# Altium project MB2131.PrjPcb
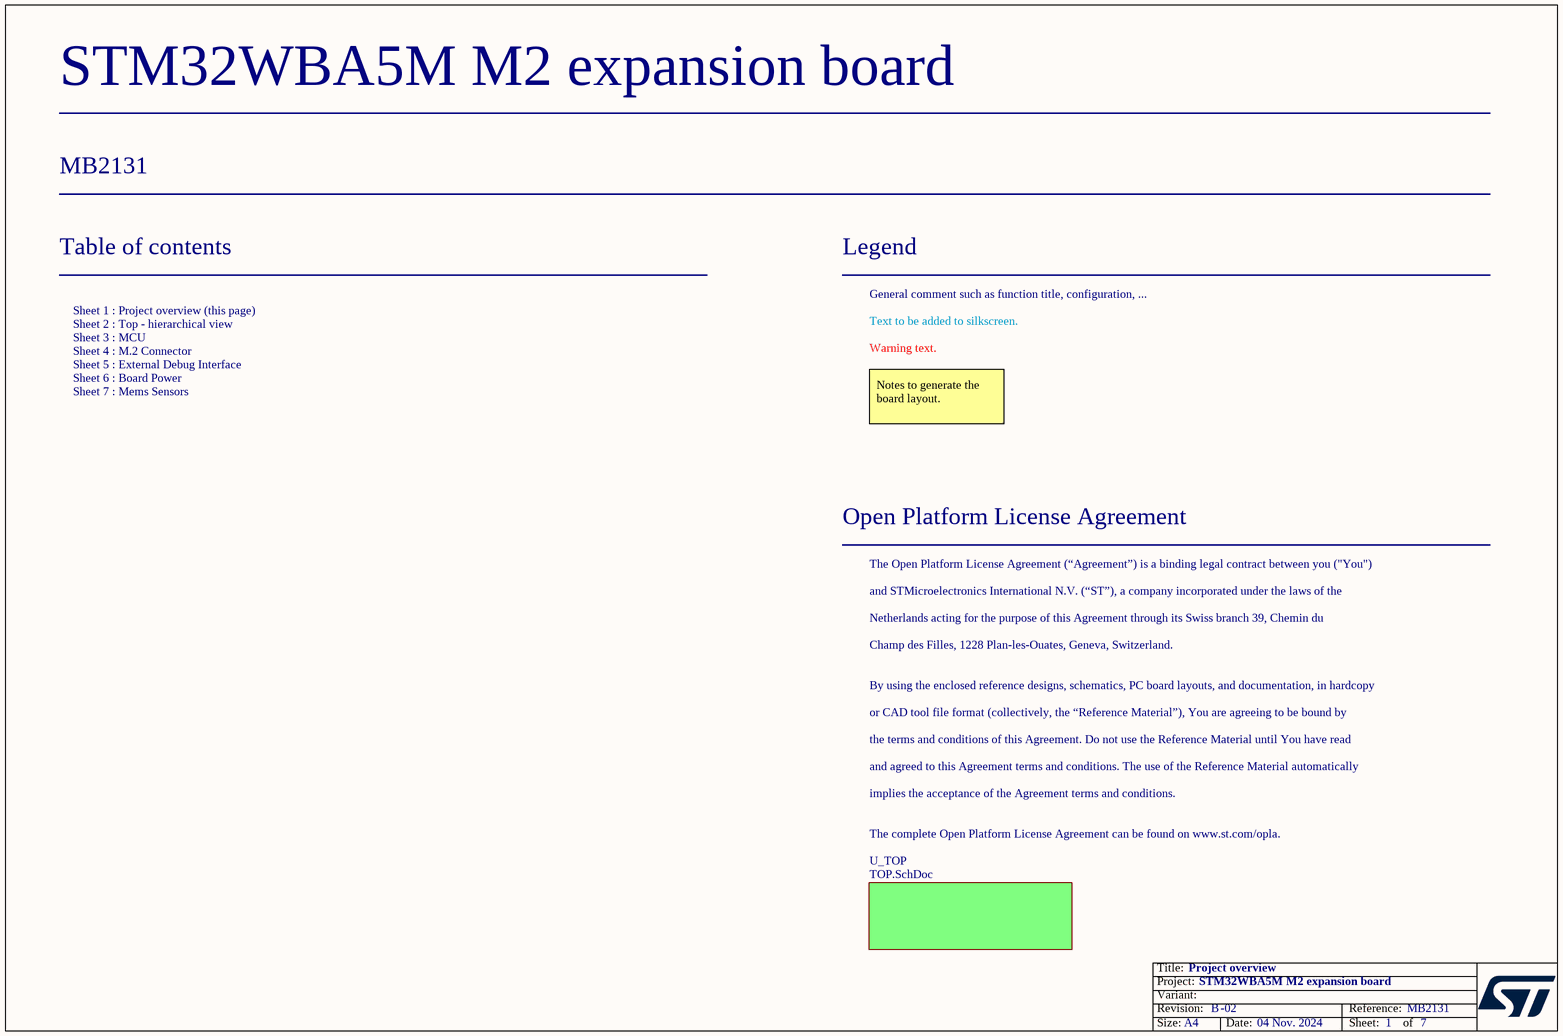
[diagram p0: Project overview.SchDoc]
Board_Assembly_Revision: 02; Board_Document_Date: 04 Nov. 2024; Board_Name: STM32WBA5M M2 expansion board; Board_PCB_Revision: B; Board_Reference: MB2131
7 sheets, 81 parts. Net scope: flat (ports and power ports of the same name join across sheets).
Board file: MB2131.PcbDoc
Sheets:
  Project overview.SchDoc
    U_TOP = Top.SchDoc
      U_MCU = MCU.SchDoc
      U_Board_Power = Board_Power.SchDoc
      U_External_Debug_Interface = External_Debug_Interface.SchDoc
      U_Mems = Mems.SchDoc
      U_M2 = M2.SchDoc

## Sheet Project overview.SchDoc: Project overview
size A4; Date: Not used; ApprovedBy: Not used; CheckedBy: Not used; Author: Not used; CompanyName: STMicroelectronics; DrawnBy: Not used; Engineer: Not used; Organization: Not used; Address1: Not used; Address2: Not used; Address3: Not used; Address4: Not used; DocumentNumber: 1; Revision: Not used; SheetNumber: 1; SheetTotal: 7

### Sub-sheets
U_TOP = TOP.SchDoc: no entries

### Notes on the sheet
- Table of contents
- Legend
- General comment such as function title, configuration, ...
- Text to be added to silkscreen.
- Warning text.
- Notes to generate the board layout.
- Open Platform License Agreement
- The Open Platform License Agreement (“Agreement”) is a binding legal contract between you ("You")
- and STMicroelectronics International N.V. (“ST”), a company incorporated under the laws of the
- Netherlands acting for the purpose of this Agreement through its Swiss branch 39, Chemin du
- Champ des Filles, 1228 Plan-les-Ouates, Geneva, Switzerland.
- Sheet 1 : Project overview (this page)
  Sheet 2 : Top - hierarchical view
  Sheet 3 : MCU
  Sheet 4 : M.2 Connector
  Sheet 5 : External Debug Interface
  Sheet 6 : Board Power
  Sheet 7 : Mems Sensors
- By using the enclosed reference designs, schematics, PC board layouts, and documentation, in hardcopy
- or CAD tool file format (collectively, the “Reference Material”), You are agreeing to be bound by
- the terms and conditions of this Agreement. Do not use the Reference Material until You have read
- and agreed to this Agreement terms and conditions. The use of the Reference Material automatically
- implies the acceptance of the Agreement terms and conditions.
- The complete Open Platform License Agreement can be found on www.st.com/opla.

## Sheet Top.SchDoc: Top - hierarchical view
size A4; Date: Not used; ApprovedBy: Not used; CheckedBy: Not used; Author: Not used; CompanyName: STMicroelectronics; DrawnBy: Not used; Engineer: Not used; Organization: Not used; Address1: Not used; Address2: Not used; Address3: Not used; Address4: Not used; DocumentNumber: Not used; Revision: Not used; SheetNumber: 2; SheetTotal: 7
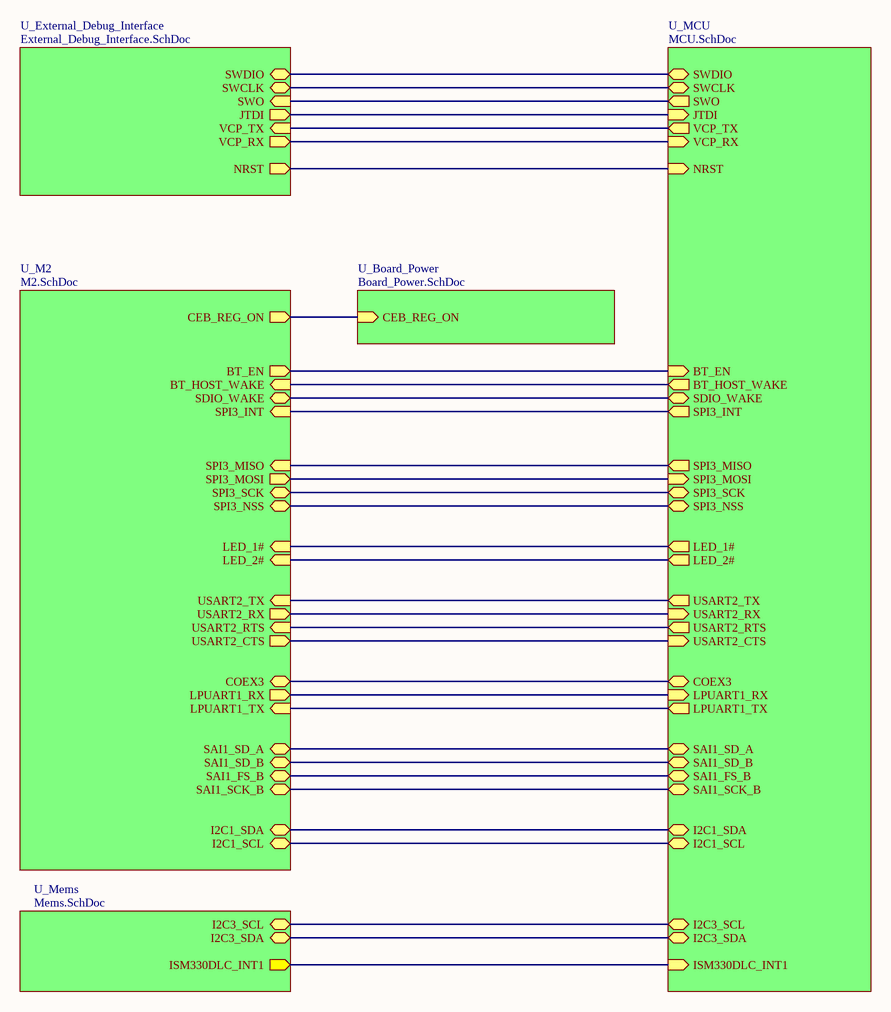
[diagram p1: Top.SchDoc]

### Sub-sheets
U_Board_Power = Board_Power.SchDoc: CEB_REG_ON (in)
U_External_Debug_Interface = External_Debug_Interface.SchDoc: SWDIO (bidir), SWCLK (bidir), SWO (in), JTDI (out), VCP_TX (in), NRST (out), VCP_RX (out)
U_M2 = M2.SchDoc: SPI3_SCK (bidir), SPI3_MISO (in), SPI3_NSS (bidir), SPI3_MOSI (out), BT_HOST_WAKE (in), SPI3_INT (in), SAI1_SD_B (bidir), SAI1_SD_A (bidir), SAI1_FS_B (bidir), SAI1_SCK_B (bidir), LED_2# (in), LED_1# (in), COEX3 (bidir), LPUART1_RX (out), LPUART1_TX (in), SDIO_WAKE (bidir), CEB_REG_ON (out), BT_EN (out), USART2_RX (out), USART2_RTS (in), USART2_CTS (out), USART2_TX (in), I2C1_SDA (bidir), I2C1_SCL (bidir)
U_MCU = MCU.SchDoc: ISM330DLC_INT1 (in), I2C3_SCL (bidir), I2C3_SDA (bidir), SWCLK (bidir), SWDIO (bidir), VCP_TX (out), VCP_RX (in), SPI3_SCK (bidir), SPI3_MISO (out), SPI3_NSS (bidir), SPI3_MOSI (in), SWO (out), JTDI (in), SPI3_INT (out), BT_HOST_WAKE (out), SAI1_SD_B (bidir), SAI1_SD_A (bidir), SAI1_FS_B (bidir), SAI1_SCK_B (bidir), LED_1# (out), LED_2# (out), COEX3 (bidir), LPUART1_RX (in), LPUART1_TX (out), SDIO_WAKE (bidir), NRST (in), BT_EN (in), USART2_RX (in), USART2_RTS (out), USART2_CTS (in), USART2_TX (out), I2C1_SCL (bidir), I2C1_SDA (bidir)
U_Mems = Mems.SchDoc: ISM330DLC_INT1 (out), I2C3_SCL (bidir), I2C3_SDA (bidir)

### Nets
(unnamed): sheet U_MCU/ISM330DLC_INT1, sheet U_Mems/ISM330DLC_INT1
(unnamed): sheet U_MCU/I2C3_SCL, sheet U_Mems/I2C3_SCL  [a separate net that carries the same name]
(unnamed): sheet U_MCU/I2C3_SDA, sheet U_Mems/I2C3_SDA  [a separate net that carries the same name]
(unnamed): sheet U_MCU/SWCLK, sheet U_External_Debug_Interface/SWCLK  [a separate net that carries the same name]
(unnamed): sheet U_MCU/SWDIO, sheet U_External_Debug_Interface/SWDIO  [a separate net that carries the same name]
(unnamed): sheet U_MCU/VCP_TX, sheet U_External_Debug_Interface/VCP_TX  [a separate net that carries the same name]
(unnamed): sheet U_MCU/VCP_RX, sheet U_External_Debug_Interface/VCP_RX  [a separate net that carries the same name]
(unnamed): sheet U_MCU/SPI3_SCK, sheet U_M2/SPI3_SCK  [a separate net that carries the same name]
(unnamed): sheet U_MCU/SPI3_MISO, sheet U_M2/SPI3_MISO  [a separate net that carries the same name]
(unnamed): sheet U_MCU/SPI3_NSS, sheet U_M2/SPI3_NSS  [a separate net that carries the same name]
(unnamed): sheet U_MCU/SPI3_MOSI, sheet U_M2/SPI3_MOSI  [a separate net that carries the same name]
(unnamed): sheet U_MCU/SWO, sheet U_External_Debug_Interface/SWO  [a separate net that carries the same name]
(unnamed): sheet U_MCU/JTDI, sheet U_External_Debug_Interface/JTDI  [a separate net that carries the same name]
(unnamed): sheet U_MCU/SPI3_INT, sheet U_M2/SPI3_INT  [a separate net that carries the same name]
(unnamed): sheet U_MCU/BT_HOST_WAKE, sheet U_M2/BT_HOST_WAKE  [a separate net that carries the same name]
(unnamed): sheet U_MCU/SAI1_SD_B, sheet U_M2/SAI1_SD_B  [a separate net that carries the same name]
(unnamed): sheet U_MCU/SAI1_SD_A, sheet U_M2/SAI1_SD_A  [a separate net that carries the same name]
(unnamed): sheet U_MCU/SAI1_FS_B, sheet U_M2/SAI1_FS_B  [a separate net that carries the same name]
(unnamed): sheet U_MCU/SAI1_SCK_B, sheet U_M2/SAI1_SCK_B  [a separate net that carries the same name]
(unnamed): sheet U_MCU/LED_1#, sheet U_M2/LED_1#  [a separate net that carries the same name]
(unnamed): sheet U_MCU/LED_2#, sheet U_M2/LED_2#  [a separate net that carries the same name]
(unnamed): sheet U_MCU/COEX3, sheet U_M2/COEX3  [a separate net that carries the same name]
(unnamed): sheet U_MCU/LPUART1_RX, sheet U_M2/LPUART1_RX  [a separate net that carries the same name]
(unnamed): sheet U_MCU/LPUART1_TX, sheet U_M2/LPUART1_TX  [a separate net that carries the same name]
(unnamed): sheet U_MCU/SDIO_WAKE, sheet U_M2/SDIO_WAKE  [a separate net that carries the same name]
(unnamed): sheet U_MCU/NRST, sheet U_External_Debug_Interface/NRST  [a separate net that carries the same name]
(unnamed): sheet U_MCU/BT_EN, sheet U_M2/BT_EN  [a separate net that carries the same name]
(unnamed): sheet U_MCU/USART2_RX, sheet U_M2/USART2_RX  [a separate net that carries the same name]
(unnamed): sheet U_MCU/USART2_RTS, sheet U_M2/USART2_RTS  [a separate net that carries the same name]
(unnamed): sheet U_MCU/USART2_CTS, sheet U_M2/USART2_CTS  [a separate net that carries the same name]
(unnamed): sheet U_MCU/USART2_TX, sheet U_M2/USART2_TX  [a separate net that carries the same name]
(unnamed): sheet U_MCU/I2C1_SCL, sheet U_M2/I2C1_SCL  [a separate net that carries the same name]
(unnamed): sheet U_MCU/I2C1_SDA, sheet U_M2/I2C1_SDA  [a separate net that carries the same name]
(unnamed): sheet U_Board_Power/CEB_REG_ON, sheet U_M2/CEB_REG_ON  [a separate net that carries the same name]

## Sheet MCU.SchDoc: MCU
size A4; Date: Not used; ApprovedBy: Not used; CheckedBy: Not used; Author: Not used; CompanyName: STMicroelectronics; DrawnBy: Not used; Engineer: Not used; Organization: Not used; Address1: Not used; Address2: Not used; Address3: Not used; Address4: Not used; DocumentNumber: Not used; Revision: Not used; SheetNumber: 3; SheetTotal: 7
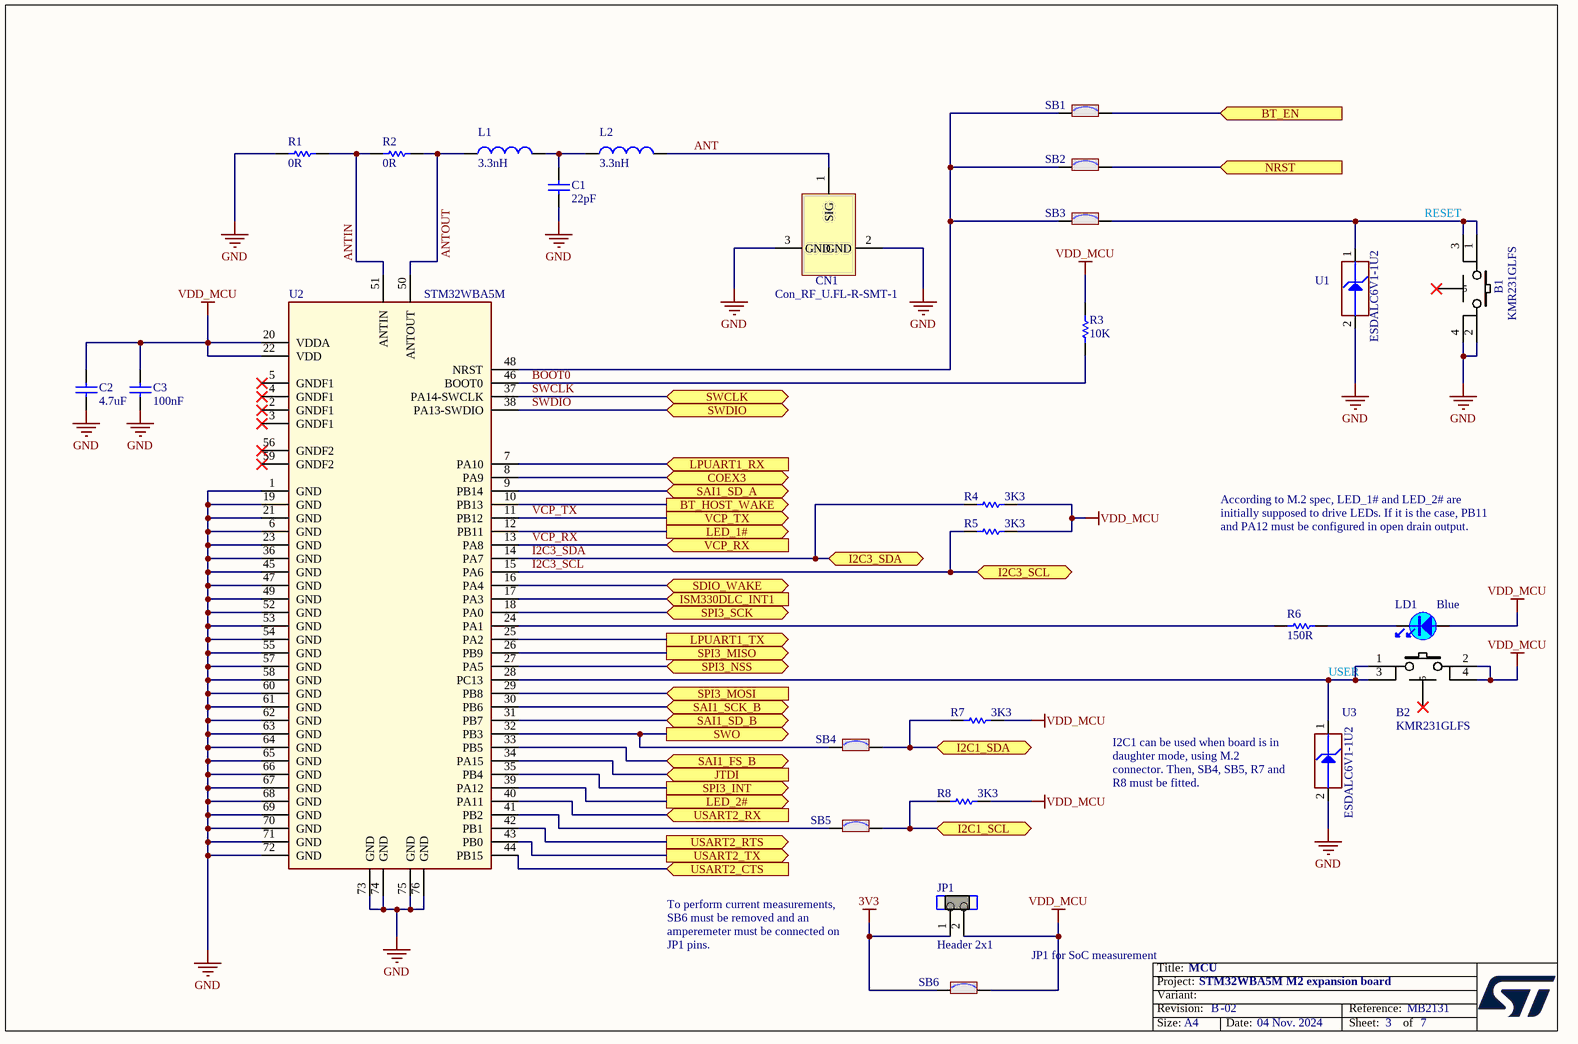
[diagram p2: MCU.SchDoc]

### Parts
B1  value KMR231GLFS  [SWI_C&K_Y78B23110FP__ITT_KMR231GLFS]  (hidden comment: SW-PUSH-CMS_KMR2_BLACK)
B2  value KMR231GLFS  [SWI_C&K_Y78B23110FP__ITT_KMR231GLFS]  (hidden comment: SW-PUSH-CMS_KMR2_BLACK)
C1  value 22pF  [C0402]  (hidden comment: Capacitor)
C2  value 4.7uF  [C0603]  (hidden comment: Capacitor)
C3  value 100nF  [C0402]  (hidden comment: Capacitor)
CN1  value Con_RF_U.FL-R-SMT-1  [CON_HRS_U.FL-R-SMT-1]  (hidden comment: U.FL-R-SMT-1)
JP1  value Header 2x1  [CON_WP_707-2-02-2-20-00]  (hidden comment: Jumper_Header1.27 2x1 Fitted)
L1  value 3.3nH  [C0402]  (hidden comment: Inductor)
L2  value 3.3nH  [C0402]  (hidden comment: Inductor)
LD1  value Blue  [LED_0603_OSRAM_LB-Q39G-L2OO-35-1_BLUE_1A2K_H0P4]  (hidden comment: LED_blue)
R1  value 0R  [R0402]  (hidden comment: Resistor)
R2  value 0R  [R0402]  (hidden comment: Resistor)
R3  value 10K  [R0402]  (hidden comment: Resistor)
R4  value 3K3  [R0402]  (hidden comment: Resistor)
R5  value 3K3  [R0402]  (hidden comment: Resistor)
R6  value 150R  [R0402]  (hidden comment: Resistor)
R7  value 3K3  [R0402]  (hidden comment: Resistor)
R8  value 3K3  [R0402]  (hidden comment: Resistor)
SB1  SB_ON  [SOLDER-BRIDGE_R0402-0R]  (value not drawn)
SB2  SB_ON  [SOLDER-BRIDGE_R0402-0R]  (value not drawn)
SB3  SB_ON  [SOLDER-BRIDGE_R0402-0R]  (value not drawn)
SB4  SB_ON  [SOLDER-BRIDGE_R0402-0R]  (value not drawn)
SB5  SB_ON  [SOLDER-BRIDGE_R0402-0R]  (value not drawn)
SB6  SB_ON  [SOLDER-BRIDGE_R0402-0R]  (value not drawn)
U1  value ESDALC6V1-1U2  [ESD_ST0201]  (hidden comment: ESD-TRANSIL)
U2  STM32WBA5M  [MOD_STM_76P_8X12P5_H1P37]
U3  value ESDALC6V1-1U2  [ESD_ST0201]  (hidden comment: ESD-TRANSIL)

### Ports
BT_EN (in), BT_HOST_WAKE (out), COEX3 (bidir), I2C1_SCL (bidir), I2C1_SDA (bidir), I2C3_SCL (bidir), I2C3_SDA (bidir), ISM330DLC_INT1 (in), JTDI (in), LED_1# (out), LED_2# (out), LPUART1_RX (in), LPUART1_TX (out), NRST (in), SAI1_FS_B (bidir), SAI1_SCK_B (bidir), SAI1_SD_A (bidir), SAI1_SD_B (bidir), SDIO_WAKE (bidir), SPI3_INT (out), SPI3_MISO (out), SPI3_MOSI (in), SPI3_NSS (bidir), SPI3_SCK (bidir), SWCLK (bidir), SWDIO (bidir), SWO (out), USART2_CTS (in), USART2_RTS (out), USART2_RX (in), USART2_TX (out), VCP_RX (in), VCP_TX (out)

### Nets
3V3: JP1.1 SB6.1
GND: B1.2 B1.4 C1.1 C2.1 C3.1 CN1.2(GND) CN1.3(GND) R1.1 U1.2(GND) U2.1(GND) U2.6(GND) U2.19(GND) U2.21(GND) U2.23(GND) U2.36(GND) U2.45(GND) U2.47(GND) U2.49(GND) U2.52(GND) U2.53(GND) U2.54(GND) U2.55(GND) U2.57(GND) U2.58(GND) U2.60(GND) U2.61(GND) U2.62(GND) U2.63(GND) U2.64(GND) U2.65(GND) U2.66(GND) U2.67(GND) U2.68(GND) U2.69(GND) U2.70(GND) U2.71(GND) U2.72(GND) U2.73(GND) U2.74(GND) U2.75(GND) U2.76(GND) U3.2(GND)
VDD_MCU: B2.2 B2.4 C2.2 C3.2 JP1.2 LD1.1 R3.2 R4.1 R5.1 R7.1 R8.1 SB6.2 U2.20(VDDA) U2.22(VDD)
ANT: CN1.1(SIG) L2.2
ANTIN: R1.2 R2.1 U2.51(ANTIN)
ANTOUT: L1.1 R2.2 U2.50(ANTOUT)
BOOT0: R3.1 U2.46(BOOT0)
I2C3_SCL: R5.2 U2.15(PA6) ; port I2C3_SCL
I2C3_SDA: R4.2 U2.14(PA7) ; port I2C3_SDA
JTDI: U2.34(PA15) ; port JTDI
NRST: SB2.2 ; port NRST
SPI3_MISO: U2.26(PB9) ; port SPI3_MISO
SPI3_MOSI: U2.29(PB8) ; port SPI3_MOSI
SPI3_NSS: U2.27(PA5) ; port SPI3_NSS
SPI3_SCK: U2.18(PA0) ; port SPI3_SCK
SWCLK: U2.37(PA14-SWCLK) ; port SWCLK
SWDIO: U2.38(PA13-SWDIO) ; port SWDIO
SWO: SB4.1 U2.32(PB3) ; port SWO
VCP_RX: U2.13(PA8) ; port VCP_RX
VCP_TX: U2.11(PB12) ; port VCP_TX
NetB1_1: B1.1 B1.3 SB3.2 U1.1(IO1)
NetB2_1: B2.1 B2.3 U2.28(PC13) U3.1(IO1)
NetC1_2: C1.2 L1.2 L2.1
NetCN2_6: U2.12(PB11) ; port LED_1#
NetCN2_8: U2.30(PB6) ; port SAI1_SCK_B
NetCN2_10: U2.33(PB5) ; port SAI1_FS_B
NetCN2_12: U2.31(PB7) ; port SAI1_SD_B
NetCN2_14: U2.9(PB14) ; port SAI1_SD_A
NetCN2_16: U2.39(PA12) ; port LED_2#
NetCN2_20: U2.10(PB13) ; port BT_HOST_WAKE
NetCN2_22: U2.43(PB0) ; port USART2_TX
NetCN2_32: U2.40(PA11) ; port USART2_RX
NetCN2_34: U2.42(PB1) ; port USART2_RTS
NetCN2_36: U2.44(PB15) ; port USART2_CTS
NetCN2_54: SB1.2 ; port BT_EN
NetCN2_58: R7.2 SB4.2 ; port I2C1_SDA
NetCN2_60: R8.2 SB5.2 ; port I2C1_SCL
NetCN2_62: U2.35(PB4) ; port SPI3_INT
NetLD1_2: LD1.2 R6.2
NetR6_1: R6.1 U2.24(PA1)
NetSB1_1: SB1.1 SB2.1 SB3.1 U2.48(NRST)
NetSB5_1: SB5.1 U2.41(PB2)
NetSB11_2: U2.16(PA4) ; port SDIO_WAKE
NetSB12_1: U2.8(PA9) ; port COEX3
NetSB13_1: U2.25(PA2) ; port LPUART1_TX
NetSB14_1: U2.7(PA10) ; port LPUART1_RX
NetU2_17: U2.17(PA3) ; port ISM330DLC_INT1

Not connected (* = marked no-connect by the designer): B1 5*; B2 5*; U2 2(GNDF1)* 3(GNDF1)* 4(GNDF1)* 5(GNDF1)* 56(GNDF2)* 59(GNDF2)*

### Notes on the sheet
- (near B1) RESET
- According to M.2 spec, LED_1# and LED_2# are initially supposed to drive LEDs. If it is the case, PB11 and PA12 must be configured in open drain output.
- USER
- (near U3) I2C1 can be used when board is in  daughter mode, using M.2 connector. Then, SB4, SB5, R7 and R8 must be fitted.
- To perform current measurements, SB6 must be removed and an amperemeter must be connected on JP1 pins.
- JP1 for SoC measurement

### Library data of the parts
B1 B2 = MCD-01485: Switch tactile, SPST-NO, 32V, 50mA, 2.8x4.6mm; Part_Type: Misc; Part_Preference: Recommended; Manufacturer: C&K; Manufacturer_HQ_COO: Unknown; Order_Code_RS: 505-9192; Component_Country_Of_Origin: France; ShowFields: YES; ID: 3585
C1 = MCD-01995: Capacitor, MLCC, 22pF, 50V, C0G, +/-5%, 0402, T=0.5mm; Part_Preference: Recommended; Manufacturer: TDK; Manufacturer_Part_Number: C1005NP01H220J050BA; Component_Country_Of_Origin: Unknown; ShowFields: YES; ID: 4095
C2 = MCD-00009: Capacitor, MLCC, 4.7uF, 16V, X5R, +/-10%, 0603, T=0.8mm; Part_Preference: Recommended; Manufacturer: YAGEO; Manufacturer_Part_Number: CC0603KRX5R7BB475; Partial_Alternate_Internal_Part_Number: MCD-03565; Component_Country_Of_Origin: China; Alternate_EMS: A; ShowFields: YES; ID: 2471
C3 = MCD-00006: Capacitor, MLCC, 100nF, 16V, X7R, +/-10%, 0402, T=0.5mm; Part_Preference: Recommended; Manufacturer: YAGEO; Manufacturer_Part_Number: CC0402KRX7R7BB104; Partial_Alternate_Internal_Part_Number: MCD-03299; Order_Code_RS: 9402047; Component_Country_Of_Origin: China; ShowFields: YES; ID: 2474
CN1 = MCD-01583: Connector_RF, 0Hz to 6GHz, 50R, VR, SMD, T= 1.25mm; BMS_Part_Number: 9187005; Part_Preference: Recommended; Manufacturer: HIROSE; Order_Code_RS: 557-981; Component_Country_Of_Origin: Japan, Malaysia; ShowFields: YES; ID: 3683
JP1 = MCD-01428: Header, 2x1, 1.27mm, RA, TH, T=3.05mm/1.27mm; Part_Type: Connector; Part_Preference: Recommended; Manufacturer: W&P PRODUCTS; Manufacturer_Part_Number: 707-2-02-2-20-00; Component_Country_Of_Origin: China; ShowFields: YES; ID: 3528
L1 L2 = MCD-03001: Inductor, 3.3nH, +/-0.3nH, 0.8A,125mR, 0402, T=0.5mm; Part_Preference: Recommended; Manufacturer: MURATA; Manufacturer_Part_Number: LQG15HS3N3S02; Component_Country_Of_Origin: Japan°; ShowFields: YES; ID: 5117
LD1 = MCD-00585: LED, Blue, 2V85, 5mA, 0603; Part_Type: Display; Part_Preference: Recommended; Manufacturer: OSRAM OPTO SEMICONDUCTORS; Manufacturer_Part_Number: LB Q39G-L2OO-35-1; Full_Alternate_Internal_Part_Number: MCD-02398; Order_Code_RS: 9148643; Component_Country_Of_Origin: Unknown; ShowFields: YES; ID: 3159
R1 R2 = MCD-00052: Resistor, 0R, 0402, +/-5%, 1/16W; Part_Preference: Recommended; Manufacturer: YAGEO; Manufacturer_Part_Number: RC0402JR-070RL; Order_Code_RS: 9232516RL; Component_Country_Of_Origin: China; ShowFields: YES; ID: 2540
R3 = MCD-00053: Resistor, 10K, 0402, +/-1%, 1/16W; BMS_Part_Number: 9131590; Part_Preference: Recommended; Manufacturer: YAGEO; Manufacturer_Part_Number: RC0402FR-0710KL; Order_Code_RS: 9239359; Component_Country_Of_Origin: China; ShowFields: YES; ID: 2539
R4 R5 R7 R8 = MCD-00184: Resistor, 3K3, 0402, +/-1%, 1/16W; BMS_Part_Number: 9131946; Part_Preference: Recommended; Manufacturer: YAGEO; Manufacturer_Part_Number: RC0402FR-073K3L; Component_Country_Of_Origin: China; ShowFields: YES; ID: 2684
R6 = MCD-00393: Resistor, 150R, 0402, +/-1%, 1/16W; Part_Preference: Recommended; Manufacturer: YAGEO; Manufacturer_Part_Number: RC0402FR-07150RL; Component_Country_Of_Origin: China; ShowFields: YES; ID: 2880
SB1-SB6 = MCD-01618: Resistor, 0R, SB0402, 5%, 0.063W; Part_Preference: Recommended; Manufacturer: YAGEO; Manufacturer_Part_Number: RC0402JR-070RL; Order_Code_RS: 618-5804; Component_Country_Of_Origin: China; ShowFields: YES; ID: 3718
U1 U3 = MCD-00170: Diode, ESD TVS, 3V, 100nA, 8V, ST0201; BMS_Part_Number: 9151132; Part_Preference: Recommended; Manufacturer: STMICROELECTRONICS; Manufacturer_HQ_COO: EU; Order_Code_RS: 795-8404; Component_Country_Of_Origin: China; ShowFields: YES; ID: 2696
U2 = MCD-03538: STM32 Module with RF  integer; Part_Type: IC; Part_Preference: Recommended; Manufacturer: STMICROELECTRONICS; Value: STM32WBA5MMGH6; Component_Country_Of_Origin: Unknown; ShowFields: YES; ID: 5654

## Sheet Board_Power.SchDoc: Board Power
size A4; Date: Not used; ApprovedBy: Not used; CheckedBy: Not used; Author: Not used; CompanyName: STMicroelectronics; DrawnBy: Not used; Engineer: Not used; Organization: Not used; Address1: Not used; Address2: Not used; Address3: Not used; Address4: Not used; DocumentNumber: Not used; Revision: Not used; SheetNumber: 6; SheetTotal: 7
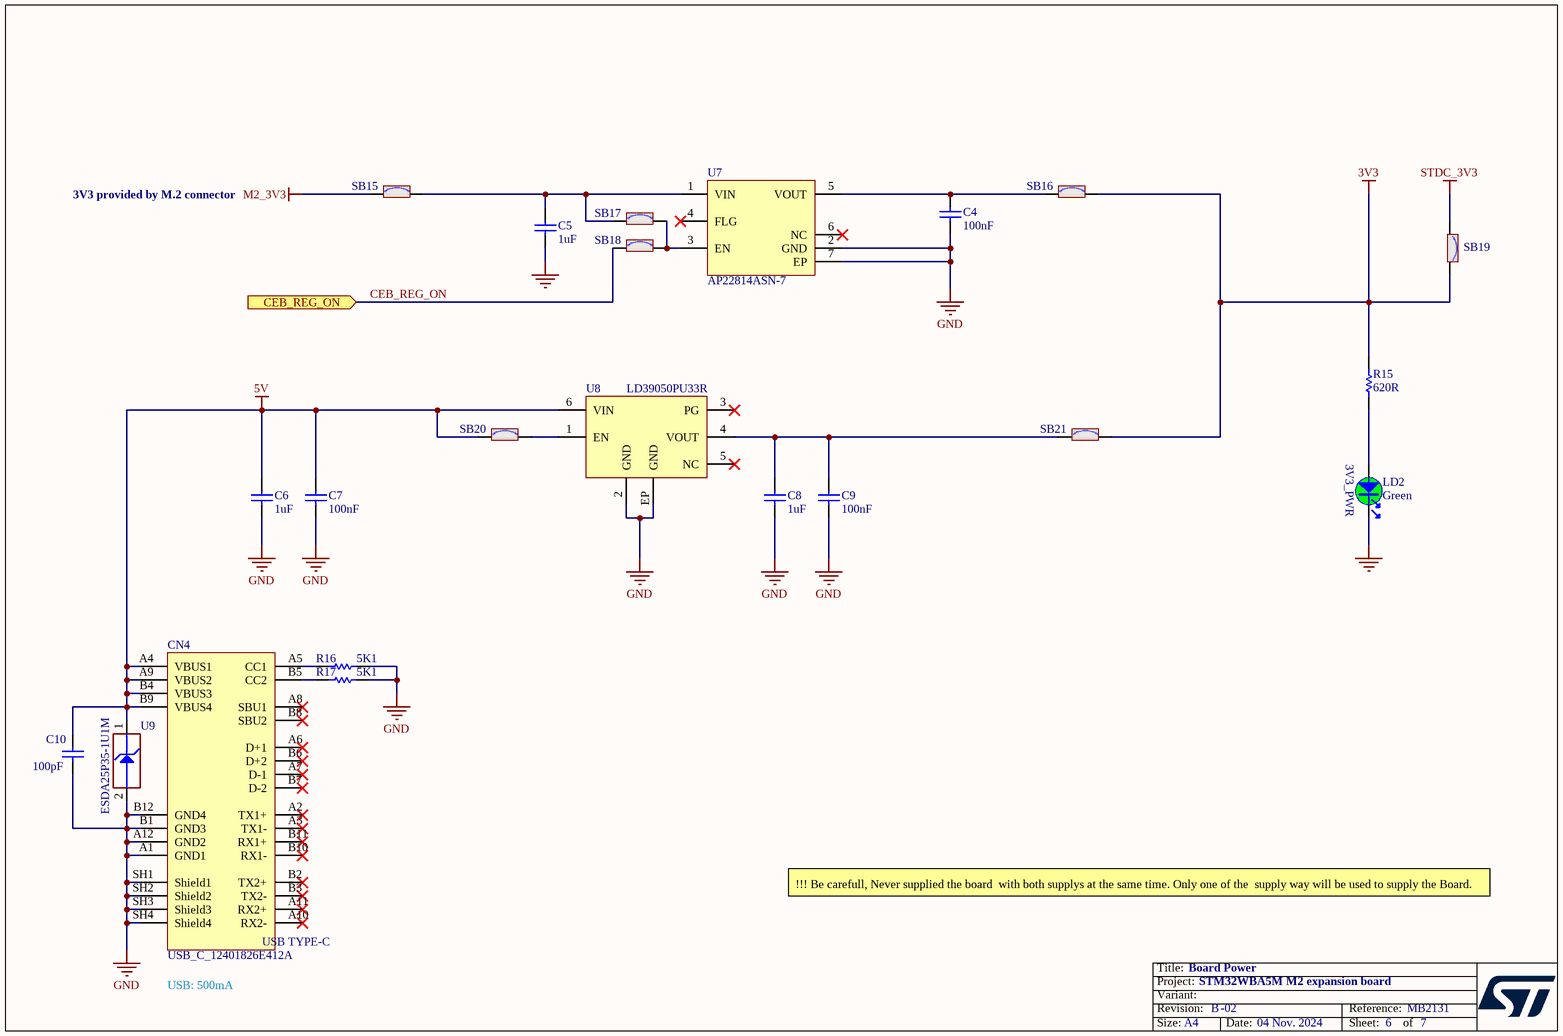
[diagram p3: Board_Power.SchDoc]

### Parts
C4  value 100nF  [C0402]  (hidden comment: Capacitor)
C5  value 1uF  [C0402]  (hidden comment: Capacitor)
C6  value 1uF  [C0402]  (hidden comment: Capacitor)
C7  value 100nF  [C0402]  (hidden comment: Capacitor)
C8  value 1uF  [C0402]  (hidden comment: Capacitor)
C9  value 100nF  [C0402]  (hidden comment: Capacitor)
C10  value 100pF  [C0402]  (hidden comment: Capacitor)
CN4  value USB_C_12401826E412A  [CON_USB-TYPEC_AMPHENOL_12401826E412A]  (hidden comment: USB_TYPE_C_Receptacle)
LD2  value Green  [LED_0603_OSRAM_LG-Q396-PS-35_GREEN_1A2K_H0P4]  (hidden comment: LED_green)
R15  value 620R  [R0402]  (hidden comment: Resistor)
R16  value 5K1  [R0402]  (hidden comment: Resistor)
R17  value 5K1  [R0402]  (hidden comment: Resistor)
SB15  SB_ON  [SOLDER-BRIDGE_R0402-0R]  (value not drawn)
SB16  SB_ON  [SOLDER-BRIDGE_R0402-0R]  (value not drawn)
SB17  SB_ON  [SOLDER-BRIDGE_R0402-0R]  (value not drawn)
SB18  SB_ON  [SOLDER-BRIDGE_R0402-0R]  (value not drawn)
SB19  SB_ON  [SOLDER-BRIDGE_R0402-0R]  (value not drawn)
SB20  SB_ON  [SOLDER-BRIDGE_R0402-0R]  (value not drawn)
SB21  SB_ON  [SOLDER-BRIDGE_R0402-0R]  (value not drawn)
U7  AP22814ASN-7  [ICC_DFN2020-6-EPAD_2X2_P065]
U8  LD39050PU33R  [ICC_DFN6-EPAD_3X3_P095]
U9  value ESDA25P35-1U1M  [ESD_QFN1610_2N_1K_2A]  (hidden comment: ESD-TRANSIL)

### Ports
CEB_REG_ON (in)

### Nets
3V3: R15.2 SB16.2 SB19.2 SB21.2
5V: C6.2 C7.2 C10.2 CN4.A4(VBUS1) CN4.A9(VBUS2) CN4.B4(VBUS3) CN4.B9(VBUS4) SB20.1 U8.6(VIN) U9.1(IO1)
GND: C4.1 C5.1 C6.1 C7.1 C8.1 C9.1 C10.1 CN4.A1(GND1) CN4.A12(GND2) CN4.B1(GND3) CN4.B12(GND4) CN4.SH1(Shield1) CN4.SH2(Shield2) CN4.SH3(Shield3) CN4.SH4(Shield4) LD2.2 R16.2 R17.2 U7.2(GND) U7.7(EP) U8.2(GND) U8.EP(GND) U9.2(GND)
M2_3V3: SB15.1
STDC_3V3: SB19.1
CEB_REG_ON: SB18.1 ; port CEB_REG_ON
NetC4_2: C4.2 SB16.1 U7.5(VOUT)
NetC5_2: C5.2 SB15.2 SB17.1 U7.1(VIN)
NetC8_2: C8.2 C9.2 SB21.1 U8.4(VOUT)
NetCN4_A5: CN4.A5(CC1) R16.1
NetCN4_B5: CN4.B5(CC2) R17.1
NetLD2_1: LD2.1 R15.1
NetSB17_2: SB17.2 SB18.2 U7.3(EN)
NetSB20_2: SB20.2 U8.1(EN)

Not connected (* = marked no-connect by the designer): CN4 A2(TX1+)* A3(TX1-)* A6(D+1)* A7(D-1)* A8(SBU1)* A10(RX2-)* A11(RX2+)* B2(TX2+)* B3(TX2-)* B6(D+2)* B7(D-2)* B8(SBU2)* B10(RX1-)* B11(RX1+)*; U7 4(FLG)* 6(NC)*; U8 3(PG)* 5(NC)*

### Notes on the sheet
- 3V3 provided by M.2 connector
- (near LD2) 3V3_PWR
- !!! Be carefull, Never supplied the board  with both supplys at the same time. Only one of the  supply way will be used to supply the Board.
- USB: 500mA

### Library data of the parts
C4 C7 C9 = MCD-00006: as C3 on sheet MCU
C5 C6 C8 = MCD-00095: Capacitor, MLCC, 1uF, 25V, X5R, +/-10%, 0402, T=0.5mm; Part_Preference: Recommended; Manufacturer: MURATA; Manufacturer_Part_Number: GRM155R61E105KA12; Order_Code_RS: 2218855; Component_Country_Of_Origin: Japan°°; ShowFields: YES; ID: 2772
C10 = MCD-00205: Capacitor, MLCC, 100pF, 50V, NPO, +/-5%, 0402, T=0.5mm; Part_Preference: Recommended; Manufacturer: YAGEO; Manufacturer_Part_Number: CC0402JRNPO9BN101; Component_Country_Of_Origin: China; ShowFields: YES; ID: 2658
CN4 = MCD-03232: USB_TypeC, 24 pins, RA, SMD, T=2.96mm; Part_Type: Connector; Part_Preference: Recommended; Manufacturer: AMPHENOL ICC; Manufacturer_Part_Number: 12401826E412A; Component_Country_Of_Origin: China°; ShowFields: YES; ID: 5348
LD2 = MCD-00588: LED, Green, 2V, 20mA, 0603; Part_Type: Display; Part_Preference: Recommended; Manufacturer: OSRAM OPTO SEMICONDUCTORS; Manufacturer_Part_Number: LG Q396-PS-35; Partial_Alternate_Internal_Part_Number: MCD-02400, MCD-03155; Component_Country_Of_Origin: Unknown; ShowFields: YES; ID: 3155
R15 = MCD-00499: Resistor, 620R, 0402, +/-1%, 1/16W; Part_Preference: Recommended; Manufacturer: YAGEO; Manufacturer_Part_Number: RC0402FR-07620RL; Component_Country_Of_Origin: China; ShowFields: YES; ID: 2781
R16 R17 = MCD-00333: Resistor, 5K1, 0402, +/-1%, 1/16W; Part_Preference: Recommended; Manufacturer: YAGEO; Manufacturer_Part_Number: RC0402FR-075K1L; Component_Country_Of_Origin: China; ShowFields: YES; ID: 2944
SB15-SB21 = MCD-01618: as SB1 on sheet MCU
U7 = MCD-02963: IC, Power Switch, 2V7 to 5V5, 3A; Part_Preference: Recommended; Manufacturer: DIODES INCORPORATED; Order_Code_RS: 1464894P; Component_Country_Of_Origin: China°; ShowFields: YES; ID: 5079
U8 = MCD-00215: LDO, 500mA, Low quiescent current and low noise voltage regulator; BMS_Part_Number: 9176126; Part_Type: IC; Part_Preference: Recommended; Manufacturer: STMICROELECTRONICS; Manufacturer_HQ_COO: NEC; Order_Code_RS: 196-1948; Component_Country_Of_Origin: Malaysia; ShowFields: YES; ID: 2654
U9 = MCD-01207: Diode, ESD TVS, 22V, 200nA, 25V8, QFN1610; BMS_Part_Number: 9179045; Part_Preference: Recommended; Manufacturer: STMICROELECTRONICS; Manufacturer_HQ_COO: EU; Order_Code_RS: 163-9774; Component_Country_Of_Origin: China; ShowFields: YES; ID: 3289

## Sheet External_Debug_Interface.SchDoc: External Debug Interface
size A4; Date: Not used; ApprovedBy: Not used; CheckedBy: Not used; Author: Not used; CompanyName: STMicroelectronics; DrawnBy: Not used; Engineer: Not used; Organization: Not used; Address1: Not used; Address2: Not used; Address3: Not used; Address4: Not used; DocumentNumber: Not used; Revision: Not used; SheetNumber: 5; SheetTotal: 7
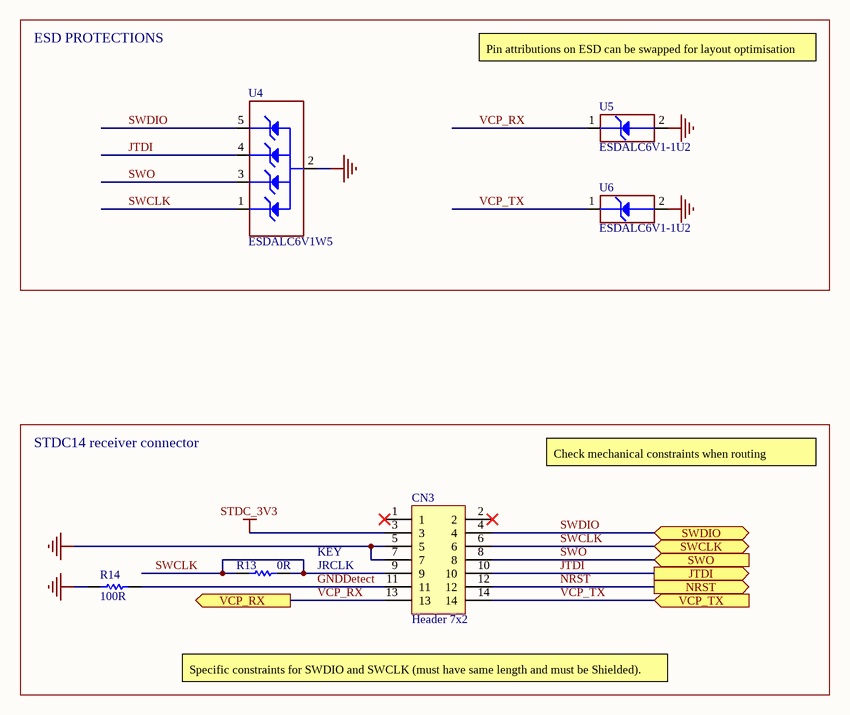
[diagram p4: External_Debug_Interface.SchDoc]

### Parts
CN3  Header 7x2  [CON_STDC14_Receiver_SMALL]
R13  value 0R  [R0402]  (hidden comment: Resistor)
R14  value 100R  [R0402]  (hidden comment: Resistor)
U4  ESDALC6V1W5  [ESD_SOT323-5L]
U5  value ESDALC6V1-1U2  [ESD_ST0201]  (hidden comment: ESD-TRANSIL)
U6  value ESDALC6V1-1U2  [ESD_ST0201]  (hidden comment: ESD-TRANSIL)

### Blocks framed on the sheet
ESD PROTECTIONS: U4-U6
STDC14 receiver connector: CN3 R13 R14

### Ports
JTDI (out), NRST (out), SWCLK (bidir), SWDIO (bidir), SWO (in), VCP_RX (out), VCP_TX (in)

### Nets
GND: CN3.5 CN3.7 R14.1 U4.2(GND) U5.2(GND) U6.2(GND)
STDC_3V3: CN3.3
GNDDetect: CN3.11 R14.2
JTDI: CN3.10 U4.4(IO3) ; port JTDI
NRST: CN3.12 ; port NRST
SWCLK: CN3.6 CN3.9 R13.1 R13.2 U4.1(IO1) ; port SWCLK
SWDIO: CN3.4 U4.5(IO4) ; port SWDIO
SWO: CN3.8 U4.3(IO2) ; port SWO
VCP_RX: CN3.13 U5.1(IO1) ; port VCP_RX
VCP_TX: CN3.14 U6.1(IO1) ; port VCP_TX

Not connected (* = marked no-connect by the designer): CN3 1* 2*

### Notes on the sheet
- Pin attributions on ESD can be swapped for layout optimisation
- Check mechanical constraints when routing
- (near R13) KEY
- JRCLK
- Specific constraints for SWDIO and SWCLK (must have same length and must be Shielded).

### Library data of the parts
CN3 = MCD-00639: Header, 7x2, 1.27mm, VR, SMD, T=5.97mm; Part_Type: Connector; Part_Preference: Recommended; Manufacturer: SAMTEC; Manufacturer_Part_Number: FTSH-107-01-L-DV-K; Order_Code_RS: 179-8765; Component_Country_Of_Origin: China, Costa Rica, Malaysia, United States, Vietnam; ShowFields: YES; ID: 3107
R13 = MCD-00052: as R1 on sheet MCU
R14 = MCD-00067: Resistor, 100R, 0402, +/- 1%, 1/16W; Part_Preference: Recommended; Manufacturer: YAGEO; Manufacturer_Part_Number: RC0402FR-07100RL; Order_Code_RS: 9239111; Component_Country_Of_Origin: China; ShowFields: YES; ID: 2527
U4 = MCD-00136: Diode, ESD Transil, 3V, 1uA, 7V2, SOT323-5; BMS_Part_Number: 9151112; Part_Preference: Recommended; Manufacturer: STMICROELECTRONICS; Manufacturer_HQ_COO: EU; Order_Code_RS: 178-7373; Component_Country_Of_Origin: China; ShowFields: YES; ID: 2731
U5 U6 = MCD-00170: as U1 on sheet MCU

## Sheet Mems.SchDoc: Mems Sensors
size A4; Date: Not used; ApprovedBy: Not used; CheckedBy: Not used; Author: Not used; CompanyName: STMicroelectronics; DrawnBy: Not used; Engineer: Not used; Organization: Not used; Address1: Not used; Address2: Not used; Address3: Not used; Address4: Not used; DocumentNumber: Not used; Revision: Not used; SheetNumber: 7; SheetTotal: 7
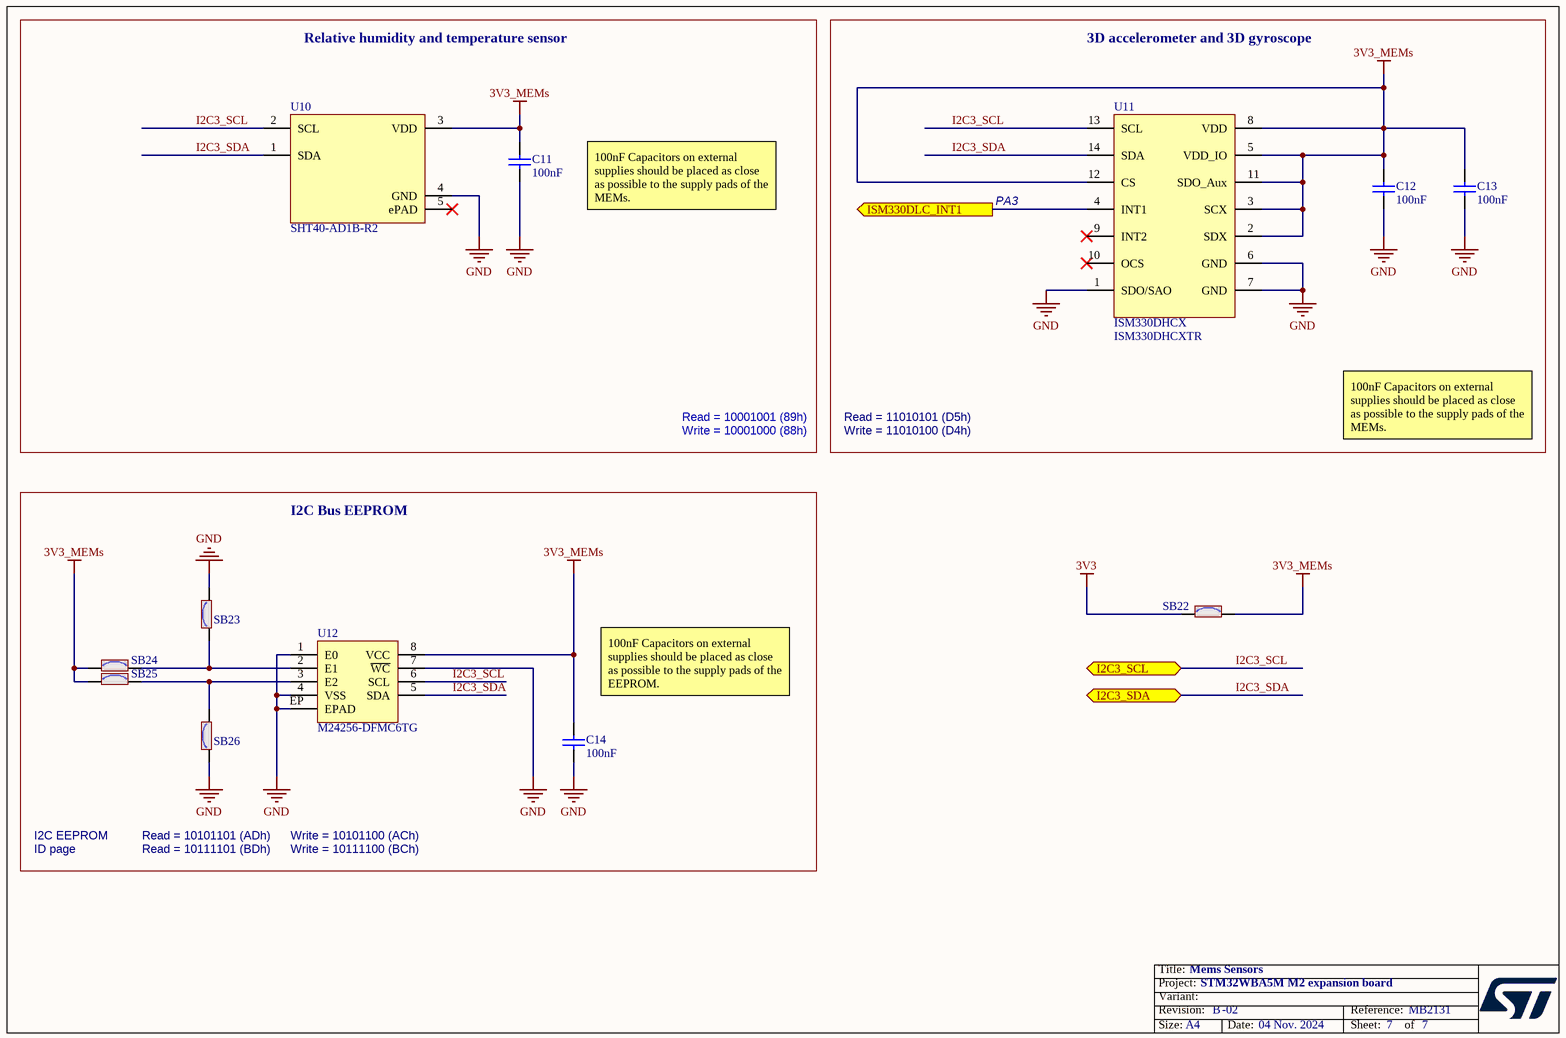
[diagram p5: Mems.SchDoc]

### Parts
C11  value 100nF  [C0402]  (hidden comment: Capacitor)
C12  value 100nF  [C0402]  (hidden comment: Capacitor)
C13  value 100nF  [C0402]  (hidden comment: Capacitor)
C14  value 100nF  [C0402]  (hidden comment: Capacitor)
SB22  SB_ON  [SOLDER-BRIDGE_R0402-0R]  (value not drawn)
SB23  SB_ON  [SOLDER-BRIDGE_R0402-0R]  (value not drawn)
SB24  SB_ON  [SOLDER-BRIDGE_R0402-0R]  (value not drawn)
SB25  SB_ON  [SOLDER-BRIDGE_R0402-0R]  (value not drawn)
SB26  SB_ON  [SOLDER-BRIDGE_R0402-0R]  (value not drawn)
U10  value SHT40-AD1B-R2  [ICC_SENSOR_SHT40-AD1B-R2_DFN4-EPAD_1P5X1P5_P050]  (hidden comment: SHT4X)
U11  ISM330DHCX  value ISM330DHCXTR  [ICC_LGA14_3X2P5_P050]
U12  value M24256-DFMC6TG  [ICC_DFN8-EPAD_2X3_P050]  (hidden comment: M24128-DFMC6TP)

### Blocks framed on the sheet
Relative humidity and temperature sensor: C11 U10
3D accelerometer and 3D gyroscope: C12 C13 U11
I2C Bus EEPROM: C14 SB23-SB26 U12

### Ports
I2C3_SCL (bidir), I2C3_SDA (bidir), ISM330DLC_INT1 (out)

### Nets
3V3: SB22.1
3V3_MEMs: C11.2 C12.2 C13.2 C14.2 SB22.2 SB24.1 SB25.1 U10.3(VDD) U11.2(SDX) U11.3(SCX) U11.5(VDD_IO) U11.8(VDD) U11.11(SDO_Aux) U11.12(CS) U12.8(VCC)
GND: C11.1 C12.1 C13.1 C14.1 SB23.2 SB26.1 U10.4(GND) U11.1(SDO/SAO) U11.6(GND) U11.7(GND) U12.1(E0) U12.4(VSS) U12.7(~{WC}) U12.EP(EPAD)
I2C3_SCL: U10.2(SCL) U11.13(SCL) U12.6(SCL) ; port I2C3_SCL
I2C3_SDA: U10.1(SDA) U11.14(SDA) U12.5(SDA) ; port I2C3_SDA
NetSB23_1: SB23.1 SB24.2 U12.2(E1)
NetSB25_2: SB25.2 SB26.2 U12.3(E2)
NetU2_17: U11.4(INT1) ; port ISM330DLC_INT1

Not connected (* = marked no-connect by the designer): U10 5(ePAD)*; U11 9(INT2)* 10(OCS)*

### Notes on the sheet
- 100nF Capacitors on external supplies should be placed as close as possible to the supply pads of the MEMs.
- PA3
- Read = 10001001 (89h)
- Write = 10001000 (88h)
- Read = 11010101 (D5h)
- Write = 11010100 (D4h)
- (near C14) 100nF Capacitors on external supplies should be placed as close as possible to the supply pads of the EEPROM.
- I2C EEPROM
- ID page
- Read = 10101101 (ADh)
- Read = 10111101 (BDh)
- Write = 10101100 (ACh)
- Write = 10111100 (BCh)

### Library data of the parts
C11-C14 = MCD-00006: as C3 on sheet MCU
SB22-SB26 = MCD-01618: as SB1 on sheet MCU
U10 = MCD-03381: Sensor, High-Accuracy, Ultra-Low-Power, 16-bit  Relative Humidity and Temperature; Part_Type: IC; Part_Preference: Recommended; Manufacturer: SENSIRION; Order_Code_RS: 207-4760P; Component_Country_Of_Origin: China, Switzerland; ShowFields: YES; ID: 5497
U11 = MCD-02160: MEMS, iNEMO inertial module with embedded Machine Learning Core: always-on 3D accelerometer and 3D gyroscope with digital output for industrial applications; Part_Type: IC; Part_Preference: Recommended; Manufacturer: STMICROELECTRONICS; Manufacturer_HQ_COO: EU; Order_Code_RS: 193-5450; Component_Country_Of_Origin: Philippines; ShowFields: YES; ID: 4260
U12 = MCD-01871: Memory, EEPROM, 1V7 to 5V5, 256Kbit, 1MHz, DFN-8; BMS_Part_Number: 9175665; Part_Type: IC; Part_Preference: Recommended; Manufacturer: STMICROELECTRONICS; Manufacturer_HQ_COO: EU; Component_Country_Of_Origin: Philippines; ShowFields: YES; ID: 3971

## Sheet M2.SchDoc: M.2 connector
size A4; Date: Not used; ApprovedBy: Not used; CheckedBy: Not used; Author: Not used; CompanyName: STMicroelectronics; DrawnBy: Not used; Engineer: Not used; Organization: Not used; Address1: Not used; Address2: Not used; Address3: Not used; Address4: Not used; DocumentNumber: Not used; Revision: Not used; SheetNumber: 4; SheetTotal: 7
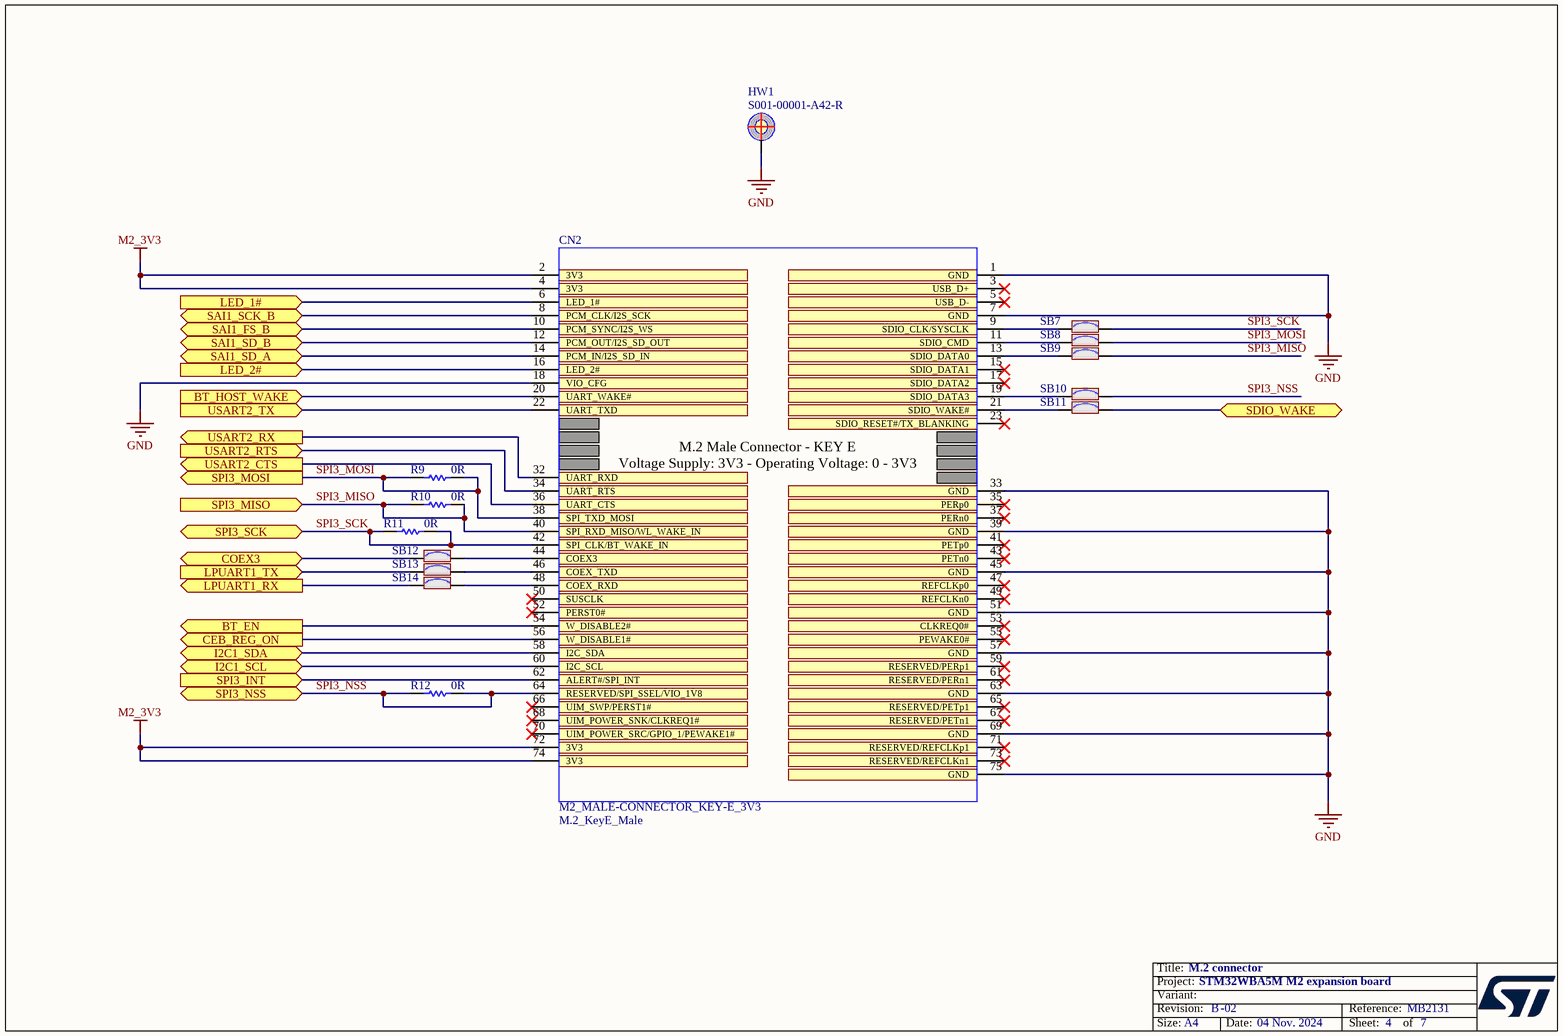
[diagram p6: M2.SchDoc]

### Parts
CN2  M2_MALE-CONNECTOR_KEY-E_3V3  value M.2_KeyE_Male  [CON_BOARD_GOLDFINGER_PCI_EXPRESS_X75_M2_KEY-E]  (no BOM)
HW1  value S001-00001-A42-R  [MISC_REGO_S001_00001_A42_R]  (hidden comment: M2_POSITION_HOLE)  (no BOM)
R9  value 0R  [R0402]  (hidden comment: Resistor)
R10  value 0R  [R0402]  (hidden comment: Resistor)
R11  value 0R  [R0402]  (hidden comment: Resistor)
R12  value 0R  [R0402]  (hidden comment: Resistor)
SB7  SB_ON  [SOLDER-BRIDGE_R0402-0R]  (value not drawn)
SB8  SB_ON  [SOLDER-BRIDGE_R0402-0R]  (value not drawn)
SB9  SB_ON  [SOLDER-BRIDGE_R0402-0R]  (value not drawn)
SB10  SB_ON  [SOLDER-BRIDGE_R0402-0R]  (value not drawn)
SB11  SB_ON  [SOLDER-BRIDGE_R0402-0R]  (value not drawn)
SB12  SB_ON  [SOLDER-BRIDGE_R0402-0R]  (value not drawn)
SB13  SB_ON  [SOLDER-BRIDGE_R0402-0R]  (value not drawn)
SB14  SB_ON  [SOLDER-BRIDGE_R0402-0R]  (value not drawn)

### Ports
BT_EN (out), BT_HOST_WAKE (in), CEB_REG_ON (out), COEX3 (bidir), I2C1_SCL (bidir), I2C1_SDA (bidir), LED_1# (in), LED_2# (in), LPUART1_RX (out), LPUART1_TX (in), SAI1_FS_B (bidir), SAI1_SCK_B (bidir), SAI1_SD_A (bidir), SAI1_SD_B (bidir), SDIO_WAKE (bidir), SPI3_INT (in), SPI3_MISO (in), SPI3_MOSI (out), SPI3_NSS (bidir), SPI3_SCK (bidir), USART2_CTS (out), USART2_RTS (in), USART2_RX (out), USART2_TX (in)

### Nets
GND: CN2.1(GND) CN2.7(GND) CN2.18(VIO_CFG) CN2.33(GND) CN2.39(GND) CN2.45(GND) CN2.51(GND) CN2.57(GND) CN2.63(GND) CN2.69(GND) CN2.75(GND) HW1.1
M2_3V3: CN2.2(3V3) CN2.4(3V3) CN2.72(3V3) CN2.74(3V3)
CEB_REG_ON: CN2.56(W_DISABLE1#) ; port CEB_REG_ON
SPI3_MISO: CN2.40(SPI_RXD_MISO/WL_WAKE_IN) R10.1 R10.2 SB9.2 ; port SPI3_MISO
SPI3_MOSI: CN2.38(SPI_TXD_MOSI) R9.1 R9.2 SB8.2 ; port SPI3_MOSI
SPI3_NSS: CN2.64(RESERVED/SPI_SSEL/VIO_1V8) R12.1 R12.2 SB10.2 ; port SPI3_NSS
SPI3_SCK: CN2.42(SPI_CLK/BT_WAKE_IN) R11.1 R11.2 SB7.2 ; port SPI3_SCK
NetCN2_6: CN2.6(LED_1#) ; port LED_1#
NetCN2_8: CN2.8(PCM_CLK/I2S_SCK) ; port SAI1_SCK_B
NetCN2_9: CN2.9(SDIO_CLK/SYSCLK) SB7.1
NetCN2_10: CN2.10(PCM_SYNC/I2S_WS) ; port SAI1_FS_B
NetCN2_11: CN2.11(SDIO_CMD) SB8.1
NetCN2_12: CN2.12(PCM_OUT/I2S_SD_OUT) ; port SAI1_SD_B
NetCN2_13: CN2.13(SDIO_DATA0) SB9.1
NetCN2_14: CN2.14(PCM_IN/I2S_SD_IN) ; port SAI1_SD_A
NetCN2_16: CN2.16(LED_2#) ; port LED_2#
NetCN2_19: CN2.19(SDIO_DATA3) SB10.1
NetCN2_20: CN2.20(UART_WAKE#) ; port BT_HOST_WAKE
NetCN2_21: CN2.21(SDIO_WAKE#) SB11.1
NetCN2_22: CN2.22(UART_TXD) ; port USART2_TX
NetCN2_32: CN2.32(UART_RXD) ; port USART2_RX
NetCN2_34: CN2.34(UART_RTS) ; port USART2_RTS
NetCN2_36: CN2.36(UART_CTS) ; port USART2_CTS
NetCN2_44: CN2.44(COEX3) SB12.2
NetCN2_46: CN2.46(COEX_TXD) SB13.2
NetCN2_48: CN2.48(COEX_RXD) SB14.2
NetCN2_54: CN2.54(W_DISABLE2#) ; port BT_EN
NetCN2_58: CN2.58(I2C_SDA) ; port I2C1_SDA
NetCN2_60: CN2.60(I2C_SCL) ; port I2C1_SCL
NetCN2_62: CN2.62(ALERT#/SPI_INT) ; port SPI3_INT
NetSB11_2: SB11.2 ; port SDIO_WAKE
NetSB12_1: SB12.1 ; port COEX3
NetSB13_1: SB13.1 ; port LPUART1_TX
NetSB14_1: SB14.1 ; port LPUART1_RX

Not connected (* = marked no-connect by the designer): CN2 3(USB_D+)* 5(USB_D-)* 15(SDIO_DATA1)* 17(SDIO_DATA2)* 23(SDIO_RESET#/TX_BLANKING)* 35(PERp0)* 37(PERn0)* 41(PETp0)* 43(PETn0)* 47(REFCLKp0)* 49(REFCLKn0)* 50(SUSCLK)* 52(PERST0#)* 53(CLKREQ0#)* 55(PEWAKE0#)* 59(RESERVED/PERp1)* 61(RESERVED/PERn1)* 65(RESERVED/PETp1)* 66(UIM_SWP/PERST1#)* 67(RESERVED/PETn1)* 68(UIM_POWER_SNK/CLKREQ1#)* 70(UIM_POWER_SRC/GPIO_1/PEWAKE1#)* 71(RESERVED/REFCLKp1)* 73(RESERVED/REFCLKn1)*

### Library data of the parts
CN2 = MCD-03876: M.2 Male connector (NGFF), 67pins, keyE; Part_Type: Misc; Part_Preference: Recommended; Component_Country_Of_Origin: Unknown; ShowFields: YES; ID: 5992
HW1 = MCD-03863: NGFF Standoff, Brass, For M2 connector 4.2mm, diameter 5.5 / 4 and screw M3x3.7; Part_Type: Misc; Part_Preference: Recommended; Manufacturer: REGO ELECTRONICS INC; Component_Country_Of_Origin: Unknown; ShowFields: YES; ID: 5979
R9-R12 = MCD-00052: as R1 on sheet MCU
SB7-SB14 = MCD-01618: as SB1 on sheet MCU

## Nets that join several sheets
3V3: MCU (JP1.1 SB6.1), Board_Power (R15.2 SB16.2 SB19.2 SB21.2), Mems (SB22.1)
GND: MCU (42 pins), Board_Power (23 pins), External_Debug_Interface (6 pins), Mems (14 pins), M2 (12 pins)
M2_3V3: Board_Power (SB15.1), M2 (CN2.2 CN2.4 CN2.72 CN2.74)
STDC_3V3: Board_Power (SB19.1), External_Debug_Interface (CN3.3)
CEB_REG_ON: Board_Power (SB18.1), M2 (CN2.56)
I2C3_SCL: MCU (R5.2 U2.15), Mems (U10.2 U11.13 U12.6)
I2C3_SDA: MCU (R4.2 U2.14), Mems (U10.1 U11.14 U12.5)
JTDI: MCU (U2.34), External_Debug_Interface (CN3.10 U4.4)
NetCN2_6: MCU (U2.12), M2 (CN2.6)
NetCN2_8: MCU (U2.30), M2 (CN2.8)
NetCN2_10: MCU (U2.33), M2 (CN2.10)
NetCN2_12: MCU (U2.31), M2 (CN2.12)
NetCN2_14: MCU (U2.9), M2 (CN2.14)
NetCN2_16: MCU (U2.39), M2 (CN2.16)
NetCN2_20: MCU (U2.10), M2 (CN2.20)
NetCN2_22: MCU (U2.43), M2 (CN2.22)
NetCN2_32: MCU (U2.40), M2 (CN2.32)
NetCN2_34: MCU (U2.42), M2 (CN2.34)
NetCN2_36: MCU (U2.44), M2 (CN2.36)
NetCN2_54: MCU (SB1.2), M2 (CN2.54)
NetCN2_58: MCU (R7.2 SB4.2), M2 (CN2.58)
NetCN2_60: MCU (R8.2 SB5.2), M2 (CN2.60)
NetCN2_62: MCU (U2.35), M2 (CN2.62)
NetSB11_2: MCU (U2.16), M2 (SB11.2)
NetSB12_1: MCU (U2.8), M2 (SB12.1)
NetSB13_1: MCU (U2.25), M2 (SB13.1)
NetSB14_1: MCU (U2.7), M2 (SB14.1)
NetU2_17: MCU (U2.17), Mems (U11.4)
NRST: MCU (SB2.2), External_Debug_Interface (CN3.12)
SPI3_MISO: MCU (U2.26), M2 (CN2.40 R10.1 R10.2 SB9.2)
SPI3_MOSI: MCU (U2.29), M2 (CN2.38 R9.1 R9.2 SB8.2)
SPI3_NSS: MCU (U2.27), M2 (CN2.64 R12.1 R12.2 SB10.2)
SPI3_SCK: MCU (U2.18), M2 (CN2.42 R11.1 R11.2 SB7.2)
SWCLK: MCU (U2.37), External_Debug_Interface (5 pins)
SWDIO: MCU (U2.38), External_Debug_Interface (CN3.4 U4.5)
SWO: MCU (SB4.1 U2.32), External_Debug_Interface (CN3.8 U4.3)
VCP_RX: MCU (U2.13), External_Debug_Interface (CN3.13 U5.1)
VCP_TX: MCU (U2.11), External_Debug_Interface (CN3.14 U6.1)

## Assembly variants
WBA5M: not fitted C1 C1 C2 C2 CN1 CN4 CN4 CN5 CN5 HW1 JP1 JP1 JP? L1 L1 L1 L2 L2 R1 R2 R3 R5 R9 R10 R11 R12 R13 SB1 SB1 SB1 SB2 SB3 SB4 SB5 SB6 SB7 SB8 SB8 SB10 SB10 SB12 SB12 SB13 SB15 SB16 SB18 SB19 SB19 SB25 SB26 SB26 SB27 SB27 SB28 SB31 SB32 SB35 SB36 SB37 SB37 SB40 SB42 SB43 SB44 SB45 SB46 SB46 SB47 SB48 SB51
